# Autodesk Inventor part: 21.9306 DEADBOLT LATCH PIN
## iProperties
Created: 2012-07
Part Number: 21.9306 DEADBOLT LATCH PIN
Document SubType Name: Modeling
Designer: Administrator
Density: 8.08 g/cm^3
Material: Stainless Steel
Mass: 15.5259 g
Surface Area: 12.4874 cm^2
Volume: 1.92152 cm^3
Author: Administrator
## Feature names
1. Base1
